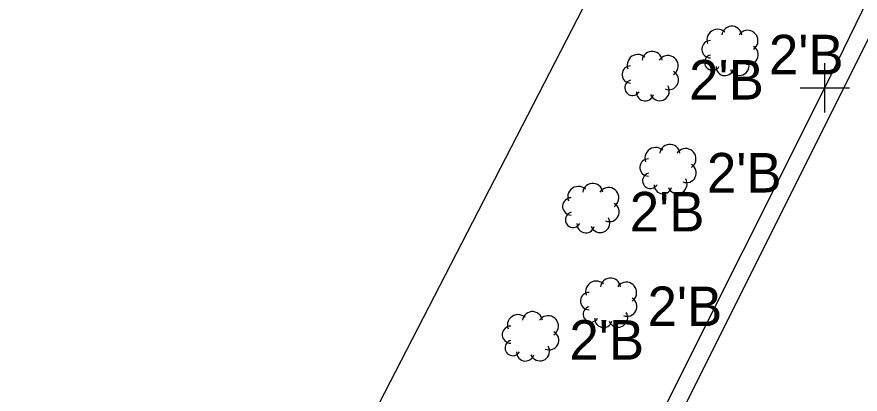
# Model space of a CAD drawing. Extents: x 1363693 to 1365209, y 422201 to 424153.
# Drawn here: x 1364106.54 to 1364140.7, y 422883.05 to 422898.3 of the extents above; entities that cross this region are included whole.
import ezdxf

# ---------------------------------------------------------------- set-up
doc = ezdxf.new("R2010")
doc.units = 0
for name, color, linetype in [('PM_X_Channelizing_Line', 7, 'Continuous'), ('PM_X_Edge_Line', 7, 'Continuous'), ('RD_X_Fence', 7, 'Continuous'), ('SV_X_Random_Point', 7, 'Continuous'), ('UT_X_FO', 7, 'Continuous'), ('VG_X_Cells', 7, 'Continuous'), ('VG_X_Flower_Bed', 7, 'Continuous'), ('VG_X_Text', 7, 'Continuous')]:
    doc.layers.add(name, color=color, linetype=linetype)

msp = doc.modelspace()

# ---------------------------------------------------------------- linework, layer by layer
at = {"layer": 'PM_X_Channelizing_Line'}
msp.add_arc((1362105.186, 424012.71), 2336.073, 330.607716, 331.220732, dxfattribs=at)
at = {"layer": 'PM_X_Edge_Line'}
msp.add_arc((1362105.186, 424012.71), 2336.073, 330.607716, 331.220732, dxfattribs=at)
at = {"layer": 'RD_X_Fence'}
msp.add_line((1364118.947, 422878.272), (1364130.072, 422899.807), dxfattribs=at)
at = {"layer": 'SV_X_Random_Point'}
for p, q in [((1364139.267, 422894.428), (1364139.267, 422896.428)), ((1364138.267, 422895.428), (1364140.267, 422895.428))]:
    msp.add_line(p, q, dxfattribs=at)
at = {"layer": 'UT_X_FO'}
msp.add_lwpolyline([(1364198.41, 423083.145), (1364202.916, 423079.215), (1364206.614, 423072.625), (1364206.927, 423065.384), (1364205.607, 423052.889), (1364202.652, 423033.176), (1364193.585, 423006.537), (1364182.955, 422981.103), (1364130.325, 422876.058), (1364040.63, 422724.214)], dxfattribs=at)
at = {"layer": 'VG_X_Cells'}
for points in [[(1364135.212, 422897.687), (1364135.147, 422897.736), (1364135.074, 422897.771), (1364134.995, 422897.793), (1364134.913, 422897.799), (1364134.832, 422897.789), (1364134.754, 422897.765), (1364134.683, 422897.726), (1364134.619, 422897.675), (1364134.567, 422897.612), (1364134.527, 422897.541), (1364134.501, 422897.464), (1364134.491, 422897.383), (1364134.496, 422897.301), (1364134.516, 422897.222)], [(1364135.909, 422897.571), (1364135.89, 422897.646), (1364135.858, 422897.717), (1364135.813, 422897.781), (1364135.756, 422897.835), (1364135.691, 422897.877), (1364135.618, 422897.906), (1364135.542, 422897.921), (1364135.463, 422897.921), (1364135.387, 422897.906), (1364135.314, 422897.877), (1364135.249, 422897.835), (1364135.192, 422897.781), (1364135.147, 422897.717), (1364135.114, 422897.646), (1364135.096, 422897.571)], [(1364136.373, 422896.99), (1364136.434, 422897.039), (1364136.484, 422897.098), (1364136.523, 422897.166), (1364136.548, 422897.24), (1364136.559, 422897.316), (1364136.556, 422897.394), (1364136.538, 422897.47), (1364136.507, 422897.541), (1364136.463, 422897.606), (1364136.408, 422897.661), (1364136.344, 422897.704), (1364136.273, 422897.736), (1364136.197, 422897.753), (1364136.119, 422897.756), (1364136.042, 422897.745), (1364135.969, 422897.72), (1364135.901, 422897.681), (1364135.842, 422897.631), (1364135.793, 422897.571)], [(1364134.632, 422897.338), (1364134.568, 422897.332), (1364134.506, 422897.315), (1364134.448, 422897.286), (1364134.397, 422897.247), (1364134.354, 422897.2), (1364134.32, 422897.145), (1364134.297, 422897.085), (1364134.285, 422897.022), (1364134.285, 422896.958), (1364134.297, 422896.895), (1364134.32, 422896.835), (1364134.354, 422896.78), (1364134.397, 422896.733), (1364134.448, 422896.694), (1364134.506, 422896.665), (1364134.568, 422896.648), (1364134.632, 422896.642)], [(1364136.025, 422896.409), (1364136.095, 422896.386), (1364136.169, 422896.376), (1364136.243, 422896.381), (1364136.315, 422896.399), (1364136.382, 422896.431), (1364136.441, 422896.475), (1364136.492, 422896.529), (1364136.531, 422896.592), (1364136.558, 422896.661), (1364136.571, 422896.734), (1364136.57, 422896.808), (1364136.555, 422896.881), (1364136.527, 422896.949), (1364136.486, 422897.011), (1364136.434, 422897.064), (1364136.373, 422897.106)], [(1364131.981, 422896.666), (1364131.916, 422896.715), (1364131.843, 422896.75), (1364131.764, 422896.772), (1364131.682, 422896.778), (1364131.601, 422896.768), (1364131.523, 422896.744), (1364131.452, 422896.705), (1364131.388, 422896.654), (1364131.336, 422896.591), (1364131.296, 422896.52), (1364131.27, 422896.443), (1364131.26, 422896.362), (1364131.265, 422896.28), (1364131.285, 422896.201)], [(1364132.678, 422896.55), (1364132.659, 422896.625), (1364132.627, 422896.696), (1364132.582, 422896.76), (1364132.525, 422896.814), (1364132.46, 422896.856), (1364132.387, 422896.885), (1364132.311, 422896.9), (1364132.232, 422896.9), (1364132.156, 422896.885), (1364132.083, 422896.856), (1364132.018, 422896.814), (1364131.961, 422896.76), (1364131.916, 422896.696), (1364131.883, 422896.625), (1364131.865, 422896.55)], [(1364133.142, 422895.969), (1364133.203, 422896.018), (1364133.253, 422896.077), (1364133.292, 422896.145), (1364133.317, 422896.219), (1364133.328, 422896.295), (1364133.325, 422896.373), (1364133.307, 422896.449), (1364133.276, 422896.52), (1364133.232, 422896.585), (1364133.177, 422896.64), (1364133.113, 422896.683), (1364133.042, 422896.715), (1364132.966, 422896.732), (1364132.888, 422896.735), (1364132.811, 422896.724), (1364132.738, 422896.699), (1364132.67, 422896.66), (1364132.611, 422896.61), (1364132.562, 422896.55)], [(1364134.632, 422896.758), (1364134.574, 422896.737), (1364134.521, 422896.705), (1364134.476, 422896.663), (1364134.44, 422896.613), (1364134.414, 422896.558), (1364134.399, 422896.498), (1364134.397, 422896.437), (1364134.406, 422896.376), (1364134.427, 422896.318), (1364134.459, 422896.266), (1364134.501, 422896.22), (1364134.55, 422896.184), (1364134.606, 422896.158), (1364134.666, 422896.143), (1364134.727, 422896.14), (1364134.788, 422896.15), (1364134.846, 422896.171), (1364134.898, 422896.202), (1364134.944, 422896.244), (1364134.98, 422896.293)], [(1364135.444, 422896.177), (1364135.479, 422896.11), (1364135.527, 422896.05), (1364135.584, 422896.001), (1364135.651, 422895.964), (1364135.723, 422895.941), (1364135.798, 422895.932), (1364135.874, 422895.937), (1364135.947, 422895.958), (1364136.015, 422895.991), (1364136.075, 422896.038), (1364136.125, 422896.095), (1364136.163, 422896.161), (1364136.188, 422896.233), (1364136.198, 422896.308), (1364136.193, 422896.384), (1364136.174, 422896.457), (1364136.141, 422896.526)], [(1364131.401, 422896.317), (1364131.337, 422896.311), (1364131.275, 422896.294), (1364131.217, 422896.265), (1364131.166, 422896.226), (1364131.123, 422896.179), (1364131.089, 422896.124), (1364131.066, 422896.064), (1364131.054, 422896.001), (1364131.054, 422895.937), (1364131.066, 422895.874), (1364131.089, 422895.814), (1364131.123, 422895.759), (1364131.166, 422895.712), (1364131.217, 422895.673), (1364131.275, 422895.644), (1364131.337, 422895.627), (1364131.401, 422895.621)], [(1364132.794, 422895.388), (1364132.864, 422895.365), (1364132.938, 422895.355), (1364133.012, 422895.36), (1364133.084, 422895.378), (1364133.151, 422895.41), (1364133.21, 422895.454), (1364133.261, 422895.508), (1364133.3, 422895.571), (1364133.327, 422895.64), (1364133.34, 422895.713), (1364133.339, 422895.787), (1364133.324, 422895.86), (1364133.296, 422895.928), (1364133.255, 422895.99), (1364133.203, 422896.043), (1364133.142, 422896.085)], [(1364134.864, 422896.293), (1364134.868, 422896.225), (1364134.885, 422896.159), (1364134.914, 422896.097), (1364134.954, 422896.041), (1364135.005, 422895.995), (1364135.063, 422895.959), (1364135.127, 422895.935), (1364135.195, 422895.924), (1364135.264, 422895.926), (1364135.33, 422895.941), (1364135.393, 422895.968), (1364135.449, 422896.007), (1364135.497, 422896.056), (1364135.535, 422896.114), (1364135.561, 422896.177)], [(1364131.401, 422895.737), (1364131.343, 422895.716), (1364131.29, 422895.684), (1364131.245, 422895.642), (1364131.209, 422895.592), (1364131.183, 422895.537), (1364131.168, 422895.477), (1364131.166, 422895.416), (1364131.175, 422895.355), (1364131.196, 422895.297), (1364131.228, 422895.245), (1364131.27, 422895.199), (1364131.319, 422895.163), (1364131.375, 422895.137), (1364131.435, 422895.122), (1364131.496, 422895.119), (1364131.557, 422895.129), (1364131.615, 422895.15), (1364131.667, 422895.181), (1364131.713, 422895.223), (1364131.749, 422895.272)], [(1364132.213, 422895.156), (1364132.248, 422895.089), (1364132.296, 422895.029), (1364132.353, 422894.98), (1364132.42, 422894.943), (1364132.492, 422894.92), (1364132.567, 422894.911), (1364132.643, 422894.916), (1364132.716, 422894.937), (1364132.784, 422894.97), (1364132.844, 422895.017), (1364132.894, 422895.074), (1364132.932, 422895.14), (1364132.957, 422895.212), (1364132.967, 422895.287), (1364132.962, 422895.363), (1364132.943, 422895.436), (1364132.91, 422895.505)], [(1364131.633, 422895.272), (1364131.637, 422895.204), (1364131.654, 422895.138), (1364131.683, 422895.076), (1364131.723, 422895.02), (1364131.774, 422894.974), (1364131.832, 422894.938), (1364131.896, 422894.914), (1364131.964, 422894.903), (1364132.033, 422894.905), (1364132.099, 422894.92), (1364132.162, 422894.947), (1364132.218, 422894.986), (1364132.266, 422895.035), (1364132.304, 422895.093), (1364132.33, 422895.156)], [(1364132.702, 422892.907), (1364132.637, 422892.956), (1364132.564, 422892.991), (1364132.485, 422893.013), (1364132.403, 422893.019), (1364132.322, 422893.009), (1364132.244, 422892.985), (1364132.173, 422892.946), (1364132.109, 422892.895), (1364132.057, 422892.832), (1364132.017, 422892.761), (1364131.991, 422892.684), (1364131.981, 422892.603), (1364131.986, 422892.521), (1364132.006, 422892.442)], [(1364133.399, 422892.791), (1364133.38, 422892.866), (1364133.348, 422892.937), (1364133.303, 422893.001), (1364133.246, 422893.055), (1364133.181, 422893.097), (1364133.108, 422893.126), (1364133.032, 422893.141), (1364132.953, 422893.141), (1364132.877, 422893.126), (1364132.804, 422893.097), (1364132.739, 422893.055), (1364132.682, 422893.001), (1364132.637, 422892.937), (1364132.604, 422892.866), (1364132.586, 422892.791)], [(1364133.863, 422892.21), (1364133.924, 422892.259), (1364133.974, 422892.318), (1364134.013, 422892.386), (1364134.038, 422892.46), (1364134.049, 422892.536), (1364134.046, 422892.614), (1364134.028, 422892.69), (1364133.997, 422892.761), (1364133.953, 422892.826), (1364133.898, 422892.881), (1364133.834, 422892.924), (1364133.763, 422892.956), (1364133.687, 422892.973), (1364133.609, 422892.976), (1364133.532, 422892.965), (1364133.459, 422892.94), (1364133.391, 422892.901), (1364133.332, 422892.851), (1364133.283, 422892.791)], [(1364132.122, 422892.558), (1364132.058, 422892.552), (1364131.996, 422892.535), (1364131.938, 422892.506), (1364131.887, 422892.467), (1364131.844, 422892.42), (1364131.81, 422892.365), (1364131.787, 422892.305), (1364131.775, 422892.242), (1364131.775, 422892.178), (1364131.787, 422892.115), (1364131.81, 422892.055), (1364131.844, 422892), (1364131.887, 422891.953), (1364131.938, 422891.914), (1364131.996, 422891.885), (1364132.058, 422891.868), (1364132.122, 422891.862)], [(1364133.515, 422891.629), (1364133.585, 422891.606), (1364133.659, 422891.596), (1364133.733, 422891.601), (1364133.805, 422891.619), (1364133.872, 422891.651), (1364133.931, 422891.695), (1364133.982, 422891.749), (1364134.021, 422891.812), (1364134.048, 422891.881), (1364134.061, 422891.954), (1364134.06, 422892.028), (1364134.045, 422892.101), (1364134.017, 422892.169), (1364133.976, 422892.231), (1364133.924, 422892.284), (1364133.863, 422892.326)], [(1364132.122, 422891.978), (1364132.064, 422891.957), (1364132.011, 422891.925), (1364131.966, 422891.883), (1364131.93, 422891.833), (1364131.904, 422891.778), (1364131.889, 422891.718), (1364131.887, 422891.657), (1364131.896, 422891.596), (1364131.917, 422891.538), (1364131.949, 422891.486), (1364131.991, 422891.44), (1364132.04, 422891.404), (1364132.096, 422891.378), (1364132.156, 422891.363), (1364132.217, 422891.36), (1364132.278, 422891.37), (1364132.336, 422891.391), (1364132.388, 422891.422), (1364132.434, 422891.464), (1364132.47, 422891.513)], [(1364132.934, 422891.397), (1364132.969, 422891.33), (1364133.017, 422891.27), (1364133.074, 422891.221), (1364133.141, 422891.184), (1364133.213, 422891.161), (1364133.288, 422891.152), (1364133.364, 422891.157), (1364133.437, 422891.178), (1364133.505, 422891.211), (1364133.565, 422891.258), (1364133.615, 422891.315), (1364133.653, 422891.381), (1364133.678, 422891.453), (1364133.688, 422891.528), (1364133.683, 422891.604), (1364133.664, 422891.677), (1364133.631, 422891.746)], [(1364129.576, 422891.332), (1364129.511, 422891.381), (1364129.438, 422891.416), (1364129.359, 422891.438), (1364129.277, 422891.444), (1364129.196, 422891.434), (1364129.118, 422891.41), (1364129.047, 422891.371), (1364128.983, 422891.32), (1364128.931, 422891.257), (1364128.891, 422891.186), (1364128.865, 422891.109), (1364128.855, 422891.028), (1364128.86, 422890.946), (1364128.88, 422890.867)], [(1364130.273, 422891.216), (1364130.254, 422891.291), (1364130.222, 422891.362), (1364130.177, 422891.426), (1364130.12, 422891.48), (1364130.055, 422891.522), (1364129.982, 422891.551), (1364129.906, 422891.566), (1364129.827, 422891.566), (1364129.751, 422891.551), (1364129.678, 422891.522), (1364129.613, 422891.48), (1364129.556, 422891.426), (1364129.511, 422891.362), (1364129.478, 422891.291), (1364129.46, 422891.216)], [(1364130.737, 422890.635), (1364130.798, 422890.684), (1364130.848, 422890.743), (1364130.887, 422890.811), (1364130.912, 422890.885), (1364130.923, 422890.961), (1364130.92, 422891.039), (1364130.902, 422891.115), (1364130.871, 422891.186), (1364130.827, 422891.251), (1364130.772, 422891.306), (1364130.708, 422891.349), (1364130.637, 422891.381), (1364130.561, 422891.398), (1364130.483, 422891.401), (1364130.406, 422891.39), (1364130.333, 422891.365), (1364130.265, 422891.326), (1364130.206, 422891.276), (1364130.157, 422891.216)], [(1364132.354, 422891.513), (1364132.358, 422891.445), (1364132.375, 422891.379), (1364132.404, 422891.317), (1364132.444, 422891.261), (1364132.495, 422891.215), (1364132.553, 422891.179), (1364132.617, 422891.155), (1364132.685, 422891.144), (1364132.754, 422891.146), (1364132.82, 422891.161), (1364132.883, 422891.188), (1364132.939, 422891.227), (1364132.987, 422891.276), (1364133.025, 422891.334), (1364133.051, 422891.397)], [(1364128.996, 422890.983), (1364128.932, 422890.977), (1364128.87, 422890.96), (1364128.812, 422890.931), (1364128.761, 422890.892), (1364128.718, 422890.845), (1364128.684, 422890.79), (1364128.661, 422890.73), (1364128.649, 422890.667), (1364128.649, 422890.603), (1364128.661, 422890.54), (1364128.684, 422890.48), (1364128.718, 422890.425), (1364128.761, 422890.378), (1364128.812, 422890.339), (1364128.87, 422890.31), (1364128.932, 422890.293), (1364128.996, 422890.287)], [(1364130.389, 422890.054), (1364130.459, 422890.031), (1364130.533, 422890.021), (1364130.607, 422890.026), (1364130.679, 422890.044), (1364130.746, 422890.076), (1364130.805, 422890.12), (1364130.856, 422890.174), (1364130.895, 422890.237), (1364130.922, 422890.306), (1364130.935, 422890.379), (1364130.934, 422890.453), (1364130.919, 422890.526), (1364130.891, 422890.594), (1364130.85, 422890.656), (1364130.798, 422890.709), (1364130.737, 422890.751)], [(1364128.996, 422890.403), (1364128.938, 422890.382), (1364128.885, 422890.35), (1364128.84, 422890.308), (1364128.804, 422890.258), (1364128.778, 422890.203), (1364128.763, 422890.143), (1364128.761, 422890.082), (1364128.77, 422890.021), (1364128.791, 422889.963), (1364128.823, 422889.911), (1364128.865, 422889.865), (1364128.914, 422889.829), (1364128.97, 422889.803), (1364129.03, 422889.788), (1364129.091, 422889.785), (1364129.152, 422889.795), (1364129.21, 422889.816), (1364129.262, 422889.847), (1364129.308, 422889.889), (1364129.344, 422889.938)], [(1364129.228, 422889.938), (1364129.232, 422889.87), (1364129.249, 422889.804), (1364129.278, 422889.742), (1364129.318, 422889.686), (1364129.369, 422889.64), (1364129.427, 422889.604), (1364129.491, 422889.58), (1364129.559, 422889.569), (1364129.628, 422889.571), (1364129.694, 422889.586), (1364129.757, 422889.613), (1364129.813, 422889.652), (1364129.861, 422889.701), (1364129.899, 422889.759), (1364129.925, 422889.822)], [(1364129.808, 422889.822), (1364129.843, 422889.755), (1364129.891, 422889.695), (1364129.948, 422889.646), (1364130.015, 422889.609), (1364130.087, 422889.586), (1364130.162, 422889.577), (1364130.238, 422889.582), (1364130.311, 422889.603), (1364130.379, 422889.636), (1364130.439, 422889.683), (1364130.489, 422889.74), (1364130.527, 422889.806), (1364130.552, 422889.878), (1364130.562, 422889.953), (1364130.557, 422890.029), (1364130.538, 422890.102), (1364130.505, 422890.171)], [(1364130.297, 422887.505), (1364130.232, 422887.554), (1364130.159, 422887.589), (1364130.08, 422887.611), (1364129.998, 422887.617), (1364129.917, 422887.607), (1364129.839, 422887.583), (1364129.768, 422887.544), (1364129.704, 422887.493), (1364129.652, 422887.43), (1364129.612, 422887.359), (1364129.586, 422887.282), (1364129.576, 422887.201), (1364129.581, 422887.119), (1364129.601, 422887.04)], [(1364130.994, 422887.389), (1364130.975, 422887.464), (1364130.943, 422887.535), (1364130.898, 422887.599), (1364130.841, 422887.653), (1364130.776, 422887.695), (1364130.703, 422887.724), (1364130.627, 422887.739), (1364130.548, 422887.739), (1364130.472, 422887.724), (1364130.399, 422887.695), (1364130.334, 422887.653), (1364130.277, 422887.599), (1364130.232, 422887.535), (1364130.199, 422887.464), (1364130.181, 422887.389)], [(1364131.458, 422886.808), (1364131.519, 422886.857), (1364131.569, 422886.916), (1364131.608, 422886.984), (1364131.633, 422887.058), (1364131.644, 422887.134), (1364131.641, 422887.212), (1364131.623, 422887.288), (1364131.592, 422887.359), (1364131.548, 422887.424), (1364131.493, 422887.479), (1364131.429, 422887.522), (1364131.358, 422887.554), (1364131.282, 422887.571), (1364131.204, 422887.574), (1364131.127, 422887.563), (1364131.054, 422887.538), (1364130.986, 422887.499), (1364130.927, 422887.449), (1364130.878, 422887.389)], [(1364129.717, 422887.156), (1364129.653, 422887.15), (1364129.591, 422887.133), (1364129.533, 422887.104), (1364129.482, 422887.065), (1364129.439, 422887.018), (1364129.405, 422886.963), (1364129.382, 422886.903), (1364129.37, 422886.84), (1364129.37, 422886.776), (1364129.382, 422886.713), (1364129.405, 422886.653), (1364129.439, 422886.598), (1364129.482, 422886.551), (1364129.533, 422886.512), (1364129.591, 422886.483), (1364129.653, 422886.466), (1364129.717, 422886.46)], [(1364131.11, 422886.227), (1364131.18, 422886.204), (1364131.254, 422886.194), (1364131.328, 422886.199), (1364131.4, 422886.217), (1364131.467, 422886.249), (1364131.526, 422886.293), (1364131.577, 422886.347), (1364131.616, 422886.41), (1364131.643, 422886.479), (1364131.656, 422886.552), (1364131.655, 422886.626), (1364131.64, 422886.699), (1364131.612, 422886.767), (1364131.571, 422886.829), (1364131.519, 422886.882), (1364131.458, 422886.924)], [(1364129.717, 422886.576), (1364129.659, 422886.555), (1364129.606, 422886.523), (1364129.561, 422886.481), (1364129.525, 422886.431), (1364129.499, 422886.376), (1364129.484, 422886.316), (1364129.482, 422886.255), (1364129.491, 422886.194), (1364129.512, 422886.136), (1364129.544, 422886.084), (1364129.586, 422886.038), (1364129.635, 422886.002), (1364129.691, 422885.976), (1364129.751, 422885.961), (1364129.812, 422885.958), (1364129.873, 422885.968), (1364129.931, 422885.989), (1364129.983, 422886.02), (1364130.029, 422886.062), (1364130.065, 422886.111)], [(1364127.132, 422886.146), (1364127.067, 422886.195), (1364126.994, 422886.23), (1364126.915, 422886.252), (1364126.833, 422886.258), (1364126.752, 422886.248), (1364126.674, 422886.224), (1364126.603, 422886.185), (1364126.539, 422886.134), (1364126.487, 422886.071), (1364126.447, 422886), (1364126.421, 422885.923), (1364126.411, 422885.842), (1364126.416, 422885.76), (1364126.436, 422885.681)], [(1364127.829, 422886.03), (1364127.81, 422886.105), (1364127.778, 422886.176), (1364127.733, 422886.24), (1364127.676, 422886.294), (1364127.611, 422886.336), (1364127.538, 422886.365), (1364127.462, 422886.38), (1364127.383, 422886.38), (1364127.307, 422886.365), (1364127.234, 422886.336), (1364127.169, 422886.294), (1364127.112, 422886.24), (1364127.067, 422886.176), (1364127.034, 422886.105), (1364127.016, 422886.03)], [(1364128.293, 422885.449), (1364128.354, 422885.498), (1364128.404, 422885.557), (1364128.443, 422885.625), (1364128.468, 422885.699), (1364128.479, 422885.775), (1364128.476, 422885.853), (1364128.458, 422885.929), (1364128.427, 422886), (1364128.383, 422886.065), (1364128.328, 422886.12), (1364128.264, 422886.163), (1364128.193, 422886.195), (1364128.117, 422886.212), (1364128.039, 422886.215), (1364127.962, 422886.204), (1364127.889, 422886.179), (1364127.821, 422886.14), (1364127.762, 422886.09), (1364127.713, 422886.03)], [(1364130.529, 422885.995), (1364130.564, 422885.928), (1364130.612, 422885.868), (1364130.669, 422885.819), (1364130.736, 422885.782), (1364130.808, 422885.759), (1364130.883, 422885.75), (1364130.959, 422885.755), (1364131.032, 422885.776), (1364131.1, 422885.809), (1364131.16, 422885.856), (1364131.21, 422885.913), (1364131.248, 422885.979), (1364131.273, 422886.051), (1364131.283, 422886.126), (1364131.278, 422886.202), (1364131.259, 422886.275), (1364131.226, 422886.344)], [(1364126.552, 422885.797), (1364126.488, 422885.791), (1364126.426, 422885.774), (1364126.368, 422885.745), (1364126.317, 422885.706), (1364126.274, 422885.659), (1364126.24, 422885.604), (1364126.217, 422885.544), (1364126.205, 422885.481), (1364126.205, 422885.417), (1364126.217, 422885.354), (1364126.24, 422885.294), (1364126.274, 422885.239), (1364126.317, 422885.192), (1364126.368, 422885.153), (1364126.426, 422885.124), (1364126.488, 422885.107), (1364126.552, 422885.101)], [(1364129.949, 422886.111), (1364129.953, 422886.043), (1364129.97, 422885.977), (1364129.999, 422885.915), (1364130.039, 422885.859), (1364130.09, 422885.813), (1364130.148, 422885.777), (1364130.212, 422885.753), (1364130.28, 422885.742), (1364130.349, 422885.744), (1364130.415, 422885.759), (1364130.478, 422885.786), (1364130.534, 422885.825), (1364130.582, 422885.874), (1364130.62, 422885.932), (1364130.646, 422885.995)], [(1364127.945, 422884.868), (1364128.015, 422884.845), (1364128.089, 422884.835), (1364128.163, 422884.84), (1364128.235, 422884.858), (1364128.302, 422884.89), (1364128.361, 422884.934), (1364128.412, 422884.988), (1364128.451, 422885.051), (1364128.478, 422885.12), (1364128.491, 422885.193), (1364128.49, 422885.267), (1364128.475, 422885.34), (1364128.447, 422885.408), (1364128.406, 422885.47), (1364128.354, 422885.523), (1364128.293, 422885.565)], [(1364126.552, 422885.217), (1364126.494, 422885.196), (1364126.441, 422885.164), (1364126.396, 422885.122), (1364126.36, 422885.072), (1364126.334, 422885.017), (1364126.319, 422884.957), (1364126.317, 422884.896), (1364126.326, 422884.835), (1364126.347, 422884.777), (1364126.379, 422884.725), (1364126.421, 422884.679), (1364126.47, 422884.643), (1364126.526, 422884.617), (1364126.586, 422884.602), (1364126.647, 422884.599), (1364126.708, 422884.609), (1364126.766, 422884.63), (1364126.818, 422884.661), (1364126.864, 422884.703), (1364126.9, 422884.752)], [(1364127.364, 422884.636), (1364127.399, 422884.569), (1364127.447, 422884.509), (1364127.504, 422884.46), (1364127.571, 422884.423), (1364127.643, 422884.4), (1364127.718, 422884.391), (1364127.794, 422884.396), (1364127.867, 422884.417), (1364127.935, 422884.45), (1364127.995, 422884.497), (1364128.045, 422884.554), (1364128.083, 422884.62), (1364128.108, 422884.692), (1364128.118, 422884.767), (1364128.113, 422884.843), (1364128.094, 422884.916), (1364128.061, 422884.985)], [(1364126.784, 422884.752), (1364126.788, 422884.684), (1364126.805, 422884.618), (1364126.834, 422884.556), (1364126.874, 422884.5), (1364126.925, 422884.454), (1364126.983, 422884.418), (1364127.047, 422884.394), (1364127.115, 422884.383), (1364127.184, 422884.385), (1364127.25, 422884.4), (1364127.313, 422884.427), (1364127.369, 422884.466), (1364127.417, 422884.515), (1364127.455, 422884.573), (1364127.481, 422884.636)]]:
    msp.add_lwpolyline(points, dxfattribs=at)
at = {"layer": 'VG_X_Flower_Bed'}
for p, q in [((1364139.267, 422895.428), (1364150.21, 422917.879)), ((1364128.07, 422873.145), (1364139.267, 422895.428))]:
    msp.add_line(p, q, dxfattribs=at)

# ---------------------------------------------------------------- texts
at = {"layer": 'VG_X_Text'}
for p in [(1364137.002, 422895.977), (1364133.771, 422894.956), (1364134.492, 422891.197), (1364131.366, 422889.622), (1364132.087, 422885.795), (1364128.922, 422884.436)]:
    msp.add_text("2'B", height=1.6, dxfattribs=at).set_placement(p)

doc.saveas('drawing.dxf')
